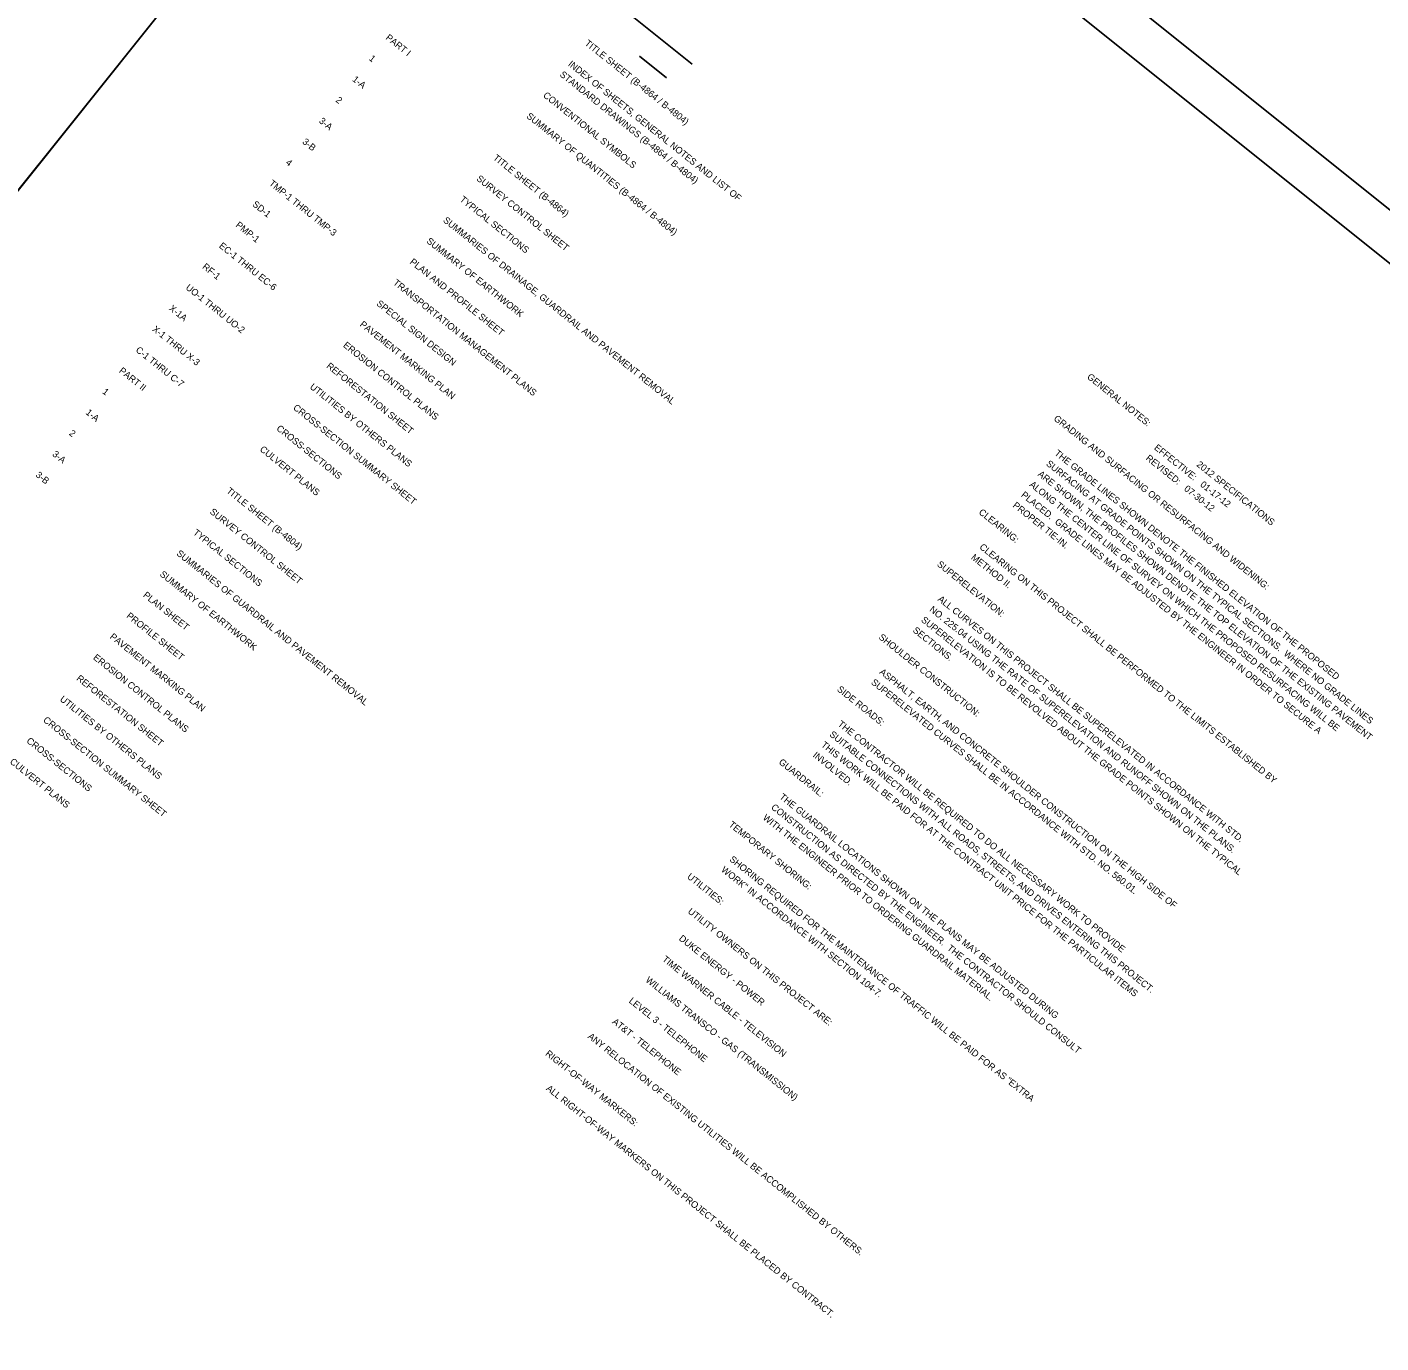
# Model space of a CAD drawing. Extents: x 1730256 to 1738218, y 910410 to 917906.
# Drawn here: x 1730764 to 1731576, y 911131 to 911921 of the extents above; entities that cross this region are included whole.
import ezdxf

# ---------------------------------------------------------------- set-up
doc = ezdxf.new("R2010")
doc.units = 0
for name, color, linetype in [('Old_Level_1', 7, 'Continuous'), ('Old_Level_18', 7, 'Continuous'), ('Old_Level_51', 7, 'Continuous')]:
    doc.layers.add(name, color=color, linetype=linetype)

msp = doc.modelspace()

# ---------------------------------------------------------------- linework, layer by layer
at = {"layer": 'Old_Level_1'}
for p, q in [((1731058.58, 912197.51), (1730571.35, 911588.71)), ((1731118.11, 911934.31), (1731163.2, 911898.22)), ((1731131.58, 911903.08), (1731147.82, 911890.09))]:
    msp.add_line(p, q, dxfattribs=at)
at = {"layer": 'Old_Level_18'}
msp.add_lwpolyline([(1732229.7, 911260.24), (1731058.58, 912197.51), (1730402.49, 911377.72), (1731573.62, 910440.45)], close=True, dxfattribs=at)
at = {"layer": 'Old_Level_51'}
msp.add_line((1732258.6, 911269.14), (1730943.82, 912321.37), dxfattribs=at)

# ---------------------------------------------------------------- texts
at = {"layer": 'Old_Level_1'}
for s, height, rotation, p in [('PART I', 4, 321.32919, (1730978.91, 911913.56)), ('TITLE SHEET (B-4864 / B-4804)', 3.9999, 321.32919, (1731098.35, 911910.19)), ('1', 4, 321.32919, (1730968.92, 911901.07)), ('INDEX OF SHEETS, GENERAL NOTES AND LIST OF', 3.9999, 321.32919, (1731088.36, 911897.7)), ('STANDARD DRAWINGS (B-4864 / B-4804)', 3.9999, 321.32919, (1731083.36, 911891.45)), ('1-A', 4, 321.32919, (1730958.92, 911888.58)), ('2', 4, 321.32919, (1730948.92, 911876.08)), ('CONVENTIONAL SYMBOLS', 3.9999, 321.32919, (1731073.36, 911878.96)), ('SUMMARY OF QUANTITIES (B-4864 / B-4804)', 3.9999, 321.32919, (1731063.36, 911866.47)), ('3-A', 4, 321.32919, (1730938.92, 911863.59)), ('3-B', 4, 321.32919, (1730928.93, 911851.1)), ('TITLE SHEET (B-4864)', 3.9999, 321.32919, (1731043.37, 911841.48)), ('4', 4, 321.32919, (1730918.93, 911838.61)), ('TMP-1 THRU TMP-3', 3.9999, 321.32919, (1730908.93, 911826.12)), ('SURVEY CONTROL SHEET', 3.9999, 321.32919, (1731033.37, 911828.99)), ('TYPICAL SECTIONS', 3.9999, 321.32919, (1731023.37, 911816.5)), ('SD-1', 4, 321.32919, (1730898.93, 911813.62)), ('PMP-1', 4, 321.32919, (1730888.94, 911801.13)), ('SUMMARIES OF DRAINAGE, GUARDRAIL AND PAVEMENT REMOVAL', 3.9999, 321.32919, (1731013.38, 911804.01)), ('EC-1 THRU EC-6', 3.9999, 321.32919, (1730878.94, 911788.64)), ('SUMMARY OF EARTHWORK', 3.9999, 321.32919, (1731003.38, 911791.51)), ('RF-1', 4, 321.32919, (1730868.94, 911776.15)), ('PLAN AND PROFILE SHEET', 3.9999, 321.32919, (1730993.38, 911779.02)), ('UO-1 THRU UO-2', 3.9999, 321.32919, (1730858.94, 911763.66)), ('TRANSPORTATION MANAGEMENT PLANS', 3.9999, 321.32919, (1730983.38, 911766.53)), ('X-1A', 4, 321.32919, (1730848.95, 911751.16)), ('SPECIAL SIGN DESIGN', 3.9999, 321.32919, (1730973.39, 911754.04)), ('X-1 THRU X-3', 3.9999, 321.32919, (1730838.95, 911738.67)), ('PAVEMENT MARKING PLAN', 3.9999, 321.32919, (1730963.39, 911741.55)), ('EROSION CONTROL PLANS', 3.9999, 321.32919, (1730953.39, 911729.05)), ('C-1 THRU C-7', 3.9999, 321.32919, (1730828.95, 911726.18)), ('PART II', 4, 321.32919, (1730818.95, 911713.69)), ('REFORESTATION SHEET', 3.9999, 321.32919, (1730943.39, 911716.56)), ('UTILITIES BY OTHERS PLANS', 3.9999, 321.32919, (1730933.4, 911704.07)), ('GENERAL NOTES:                         2012 SPECIFICATIONS', 4, 321.32968, (1731399.66, 911710.04)), ('1', 4, 321.32919, (1730808.96, 911701.2)), ('1-A', 4, 321.32919, (1730798.96, 911688.7)), ('CROSS-SECTION SUMMARY SHEET', 3.9999, 321.32919, (1730923.4, 911691.58)), ('CROSS-SECTIONS', 3.9999, 321.32919, (1730913.4, 911679.09)), ('GRADING AND SURFACING OR RESURFACING AND WIDENING:  ', 4, 321.32968, (1731379.66, 911685.05)), ('2', 4, 321.32919, (1730788.96, 911676.21)), ('3-A', 4, 321.32919, (1730778.96, 911663.72)), ('CULVERT PLANS', 3.9999, 321.32919, (1730903.4, 911666.59)), ('         THE GRADE LINES SHOWN DENOTE THE FINISHED ELEVATION OF THE PROPOSED ', 4, 321.32968, (1731369.67, 911672.56)), ('                                       EFFECTIVE:   01-17-12', 4, 321.32968, (1731394.66, 911703.79)), ('         SURFACING AT GRADE POINTS SHOWN ON THE TYPICAL SECTIONS.  WHERE NO GRADE LINES ', 4, 321.32968, (1731364.67, 911666.31)), ('                                       REVISED:   07-30-12', 4, 321.32968, (1731389.66, 911697.54)), ('3-B', 4, 321.32919, (1730768.97, 911651.23)), ('         ARE SHOWN, THE PROFILES SHOWN DENOTE THE TOP ELEVATION OF THE EXISTING PAVEMENT ', 4, 321.32968, (1731359.67, 911660.07)), ('TITLE SHEET (B-4804)', 3.9999, 321.32919, (1730883.41, 911641.61)), ('         PLACED.  GRADE LINES MAY BE ADJUSTED BY THE ENGINEER IN ORDER TO SECURE A ', 4, 321.32968, (1731349.67, 911647.58)), ('         ALONG THE CENTER LINE OF SURVEY ON WHICH THE PROPOSED RESURFACING WILL BE ', 4, 321.32968, (1731354.67, 911653.82)), ('         PROPER TIE-IN.  ', 4, 321.32968, (1731344.67, 911641.33)), ('SURVEY CONTROL SHEET', 3.9999, 321.32919, (1730873.41, 911629.12)), ('CLEARING:  ', 4, 321.32968, (1731334.68, 911628.84)), ('TYPICAL SECTIONS', 3.9999, 321.32919, (1730863.41, 911616.63)), ('         CLEARING ON THIS PROJECT SHALL BE PERFORMED TO THE LIMITS ESTABLISHED BY ', 4, 321.32968, (1731324.68, 911616.35)), ('SUMMARIES OF GUARDRAIL AND PAVEMENT REMOVAL', 3.9999, 321.32919, (1730853.42, 911604.13)), ('SUPERELEVATION:  ', 4, 321.32968, (1731309.68, 911597.61)), ('         METHOD II.', 4, 321.32968, (1731319.68, 911610.1)), ('SUMMARY OF EARTHWORK', 3.9999, 321.32919, (1730843.42, 911591.64)), ('PLAN SHEET', 4, 321.32919, (1730833.42, 911579.15)), ('         ALL CURVES ON THIS PROJECT SHALL BE SUPERELEVATED IN ACCORDANCE WITH STD. ', 4, 321.32968, (1731299.68, 911585.11)), ('PROFILE SHEET', 3.9999, 321.32919, (1730823.42, 911566.66)), ('         NO. 225.04 USING THE RATE OF SUPERELEVATION AND RUNOFF SHOWN ON THE PLANS.', 4, 321.32968, (1731294.69, 911578.87)), ('         SECTIONS.  ', 4, 321.32968, (1731284.69, 911566.38)), ('         SUPERELEVATION IS TO BE REVOLVED ABOUT THE GRADE POINTS SHOWN ON THE TYPICAL ', 4, 321.32968, (1731289.69, 911572.62)), ('PAVEMENT MARKING PLAN', 3.9999, 321.32919, (1730813.43, 911554.17)), ('SHOULDER CONSTRUCTION:  ', 4, 321.32968, (1731274.69, 911553.88)), ('EROSION CONTROL PLANS', 3.9999, 321.32919, (1730803.43, 911541.67)), ('         ASPHALT, EARTH, AND CONCRETE SHOULDER CONSTRUCTION ON THE HIGH SIDE OF', 4, 321.32968, (1731264.69, 911541.39)), ('REFORESTATION SHEET', 3.9999, 321.32919, (1730793.43, 911529.18)), ('         SUPERELEVATED CURVES SHALL BE IN ACCORDANCE WITH STD. NO. 560.01.', 4, 321.32968, (1731259.69, 911535.15)), ('UTILITIES BY OTHERS PLANS', 3.9999, 321.32919, (1730783.43, 911516.69)), ('SIDE ROADS:  ', 4, 321.32968, (1731249.7, 911522.65)), ('CROSS-SECTION SUMMARY SHEET', 3.9999, 321.32919, (1730773.44, 911504.2)), ('         THE CONTRACTOR WILL BE REQUIRED TO DO ALL NECESSARY WORK TO PROVIDE ', 4, 321.32968, (1731239.7, 911510.16)), ('         SUITABLE CONNECTIONS WITH ALL ROADS, STREETS, AND DRIVES ENTERING THIS PROJECT.  ', 4, 321.32968, (1731234.7, 911503.92)), ('CROSS-SECTIONS', 3.9999, 321.32919, (1730763.44, 911491.71)), ('         THIS WORK WILL BE PAID FOR AT THE CONTRACT UNIT PRICE FOR THE PARTICULAR ITEMS ', 4, 321.32968, (1731229.7, 911497.67)), ('CULVERT PLANS', 3.9999, 321.32919, (1730753.44, 911479.21)), ('GUARDRAIL:  ', 4, 321.32968, (1731214.71, 911478.93)), ('         INVOLVED.  ', 4, 321.32968, (1731224.7, 911491.42)), ('         CONSTRUCTION AS DIRECTED BY THE ENGINEER.  THE CONTRACTOR SHOULD CONSULT', 4, 321.32968, (1731199.71, 911460.19)), ('         THE GUARDRAIL LOCATIONS SHOWN ON THE PLANS MAY BE ADJUSTED DURING ', 4, 321.32968, (1731204.71, 911466.44)), ('         WITH THE ENGINEER PRIOR TO ORDERING GUARDRAIL MATERIAL.', 4, 321.32968, (1731194.71, 911453.95)), ('TEMPORARY SHORING:  ', 4, 321.32968, (1731184.71, 911441.46)), ('         SHORING REQUIRED FOR THE MAINTENANCE OF TRAFFIC WILL BE PAID FOR AS "EXTRA ', 4, 321.32968, (1731174.72, 911428.96)), ('UTILITIES:  ', 4, 321.32968, (1731159.72, 911410.23)), ('         WORK" IN ACCORDANCE WITH SECTION 104-7.  ', 4, 321.32968, (1731169.72, 911422.72)), ('         UTILITY OWNERS ON THIS PROJECT ARE:', 4, 321.32968, (1731149.72, 911397.73)), ('             DUKE ENERGY - POWER', 4, 321.32968, (1731139.73, 911385.24)), ('             TIME WARNER CABLE - TELEVISION', 4, 321.32968, (1731129.73, 911372.75)), ('             WILLIAMS TRANSCO - GAS (TRANSMISSION)', 4, 321.32968, (1731119.73, 911360.26)), ('             LEVEL 3 - TELEPHONE', 4, 321.32968, (1731109.73, 911347.77)), ('             AT&T - TELEPHONE', 4, 321.32968, (1731099.74, 911335.27)), ('         ANY RELOCATION OF EXISTING UTILITIES WILL BE ACCOMPLISHED BY OTHERS.  ', 4, 321.32968, (1731089.74, 911322.78)), ('RIGHT-OF-WAY MARKERS:  ', 4, 321.32968, (1731074.74, 911304.04)), ('         ALL RIGHT-OF-WAY MARKERS ON THIS PROJECT SHALL BE PLACED BY CONTRACT.  ', 4, 321.32968, (1731064.74, 911291.55))]:
    msp.add_text(s, height=height, rotation=rotation, dxfattribs=at).set_placement(p)

doc.saveas('drawing.dxf')
